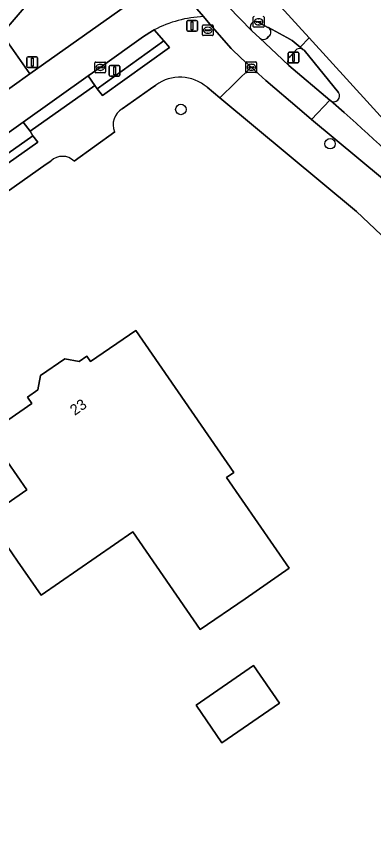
# Model space of a CAD drawing. Extents: x 161347 to 161881, y 382161 to 382804.
# Drawn here: x 161536.2 to 161569.6, y 382662 to 382738.8 of the extents above; entities that cross this region are included whole.
import ezdxf

# ---------------------------------------------------------------- set-up
doc = ezdxf.new("R2010")
doc.units = 0
for name, color, linetype in [('IMGEO_Berm_groen', 7, 'Continuous'), ('IMGEO_Boom', 7, 'Continuous'), ('IMGEO_Erf', 7, 'Continuous'), ('IMGEO_Fietspad_gesloten', 7, 'Continuous'), ('IMGEO_Groenvoorziening', 7, 'Continuous'), ('IMGEO_Haag', 7, 'Continuous'), ('IMGEO_Kolk', 7, 'Continuous'), ('IMGEO_Pand', 7, 'Continuous'), ('IMGEO_Pand_nummerreeks', 7, 'Continuous'), ('IMGEO_Rijbaan_lokaal_gesloten', 7, 'Continuous'), ('IMGEO_Rijbaan_lokaal_open', 7, 'Continuous'), ('IMGEO_Rioolput', 7, 'Continuous'), ('IMGEO_Verkeersbordpaal', 7, 'Continuous'), ('IMGEO_Verkeerseiland_groen', 7, 'Continuous'), ('IMGEO_Verkeerseiland_open', 7, 'Continuous'), ('IMGEO_Verkeersregelinstallatiepaal', 7, 'Continuous'), ('IMGEO_Voetpad_open', 7, 'Continuous')]:
    doc.layers.add(name, color=color, linetype=linetype)

msp = doc.modelspace()

# ---------------------------------------------------------------- linework, layer by layer
at = {"layer": 'IMGEO_Berm_groen'}
for points in [[(161534.886, 382737.147), (161537.494, 382733.394), (161546.454, 382739.715), (161546.949, 382740.061), (161542.143, 382745.603)], [(161537.789, 382727.63), (161537.522, 382728.039), (161536.889, 382728.907), (161530.645, 382724.485), (161516.475, 382714.369), (161503.123, 382704.778), (161491.34, 382696.368), (161486.926, 382693.195), (161487.602, 382692.215)]]:
    msp.add_lwpolyline(points, close=True, dxfattribs=at)
at = {"layer": 'IMGEO_Boom'}
for centre in [(161551.614, 382730.079), (161565.556, 382726.881)]:
    msp.add_circle(centre, 0.489, dxfattribs=at)
at = {"layer": 'IMGEO_Erf'}
for points in [[(161549.265, 382732.364), (161548.766, 382732.008), (161546.132, 382730.129)], [(161591.856, 382694.988), (161571.485, 382717.274), (161568.031, 382720.568), (161555.239, 382731.179), (161554.063, 382732.154)], [(161545.428, 382728.002), (161541.642, 382725.254)], [(161539.475, 382725.265), (161539.023, 382724.966), (161500, 382697.359), (161489.273, 382689.77), (161487.851, 382688.777), (161486.262, 382687.566), (161485.031, 382686.717), (161484.889, 382686.908), (161471.792, 382677.655), (161467.896, 382674.919)]]:
    msp.add_lwpolyline(points, dxfattribs=at)
for points in [[(161547.134, 382690.644), (161538.55, 382684.721), (161536.362, 382687.892), (161533.522, 382692.007), (161537.207, 382694.55), (161533.585, 382699.798), (161537.692, 382702.632), (161537.282, 382703.227), (161538.264, 382703.904), (161538.508, 382705.238), (161540.757, 382706.79), (161542.108, 382706.542), (161542.834, 382707.043), (161543.182, 382706.537), (161547.41, 382709.455), (161556.566, 382696.187), (161555.875, 382695.71), (161561.721, 382687.24), (161557.606, 382684.4), (161553.431, 382681.519)], [(161553.033, 382674.455), (161558.398, 382678.157), (161560.821, 382674.646), (161555.456, 382670.944)]]:
    msp.add_lwpolyline(points, close=True, dxfattribs=at)
for centre, radius, start, end in [((161551.531, 382729.212), 3.882, 49.28296, 125.70476), ((161546.958, 382728.676), 1.672, 119.61136, 203.76135), ((161540.553, 382724.161), 1.543, 45.0978, 134.32052)]:
    msp.add_arc(centre, radius, start, end, dxfattribs=at)
at = {"layer": 'IMGEO_Fietspad_gesloten'}
for points in [[(161540.187, 382749.988), (161538.613, 382748.064), (161536.523, 382745.605), (161531.663, 382739.885), (161530.446, 382738.453), (161529.536, 382737.287), (161529.183, 382736.797), (161528.989, 382736.528), (161532.246, 382733.831), (161533.12, 382735), (161534.886, 382737.147), (161542.143, 382745.603), (161544.199, 382748.164)], [(161545.564, 382748.154), (161550.263, 382742.785), (161550.342, 382742.676), (161553.736, 382738.754), (161554.324, 382738.058), (161556.318, 382735.787), (161557.247, 382734.883), (161558.194, 382734.023), (161559.548, 382732.78), (161562.685, 382730.093), (161563.827, 382729.146), (161565.541, 382730.953), (161561.715, 382734.192), (161560.548, 382735.286), (161558.99, 382736.745), (161558.259, 382737.416), (161558.212, 382737.464), (161552.779, 382743.059), (161547.812, 382748.777)], [(161566.876, 382729.794), (161565.588, 382730.912), (161565.541, 382730.953), (161563.827, 382729.146), (161570.459, 382723.644)]]:
    msp.add_lwpolyline(points, dxfattribs=at)
msp.add_arc((161490.366, 382642.402), 116.151, 42.95321, 48.79823, dxfattribs=at)
at = {"layer": 'IMGEO_Groenvoorziening'}
for points in [[(161550.024, 382736.474), (161549.126, 382737.515), (161548.976, 382737.414), (161548.114, 382736.89), (161544.081, 382734.01), (161542.938, 382733.228), (161543.561, 382732.331), (161543.803, 382732.012)], [(161550.547, 382735.868), (161550.024, 382736.474), (161543.803, 382732.012), (161544.286, 382731.374)], [(161537.789, 382727.63), (161487.602, 382692.215), (161488.093, 382691.571), (161538.259, 382727.022)]]:
    msp.add_lwpolyline(points, close=True, dxfattribs=at)
at = {"layer": 'IMGEO_Haag'}
msp.add_lwpolyline([(161550.547, 382735.868), (161550.024, 382736.474), (161543.803, 382732.012), (161544.286, 382731.374)], close=True, dxfattribs=at)
at = {"layer": 'IMGEO_Kolk'}
for p, q in [((161558.382, 382737.84), (161558.382, 382738.692)), ((161558.87, 382738.546), (161558.895, 382738.546)), ((161559.383, 382738.692), (161559.383, 382737.84)), ((161559.309, 382737.766), (161558.457, 382737.766)), ((161558.641, 382738.26), (161558.641, 382738.272)), ((161559.079, 382738.223), (161558.681, 382738.223)), ((161558.684, 382738.309), (161559.082, 382738.309)), ((161558.893, 382737.986), (161558.868, 382737.986)), ((161559.125, 382738.272), (161559.125, 382738.26)), ((161543.58, 382733.584), (161543.58, 382734.436)), ((161543.655, 382734.51), (161544.507, 382734.51)), ((161543.839, 382734.004), (161543.839, 382734.016)), ((161544.277, 382733.967), (161543.879, 382733.967)), ((161543.882, 382734.053), (161544.28, 382734.053)), ((161544.068, 382734.29), (161544.093, 382734.29)), ((161544.323, 382734.016), (161544.323, 382734.004)), ((161544.581, 382734.436), (161544.581, 382733.584)), ((161557.693, 382733.597), (161557.693, 382734.449)), ((161557.768, 382734.523), (161558.62, 382734.523)), ((161557.952, 382734.017), (161557.952, 382734.029)), ((161558.39, 382733.98), (161557.992, 382733.98)), ((161557.995, 382734.066), (161558.393, 382734.066)), ((161558.181, 382734.303), (161558.206, 382734.303)), ((161558.436, 382734.029), (161558.436, 382734.017)), ((161558.694, 382734.449), (161558.694, 382733.597)), ((161544.507, 382733.51), (161543.655, 382733.51)), ((161544.091, 382733.73), (161544.066, 382733.73)), ((161558.62, 382733.523), (161557.768, 382733.523)), ((161558.204, 382733.743), (161558.179, 382733.743))]:
    msp.add_line(p, q, dxfattribs=at)
for points in [[(161558.382, 382737.84), (161558.382, 382738.692)], [(161559.383, 382738.692), (161559.383, 382737.84)], [(161559.309, 382737.766), (161558.457, 382737.766)], [(161543.58, 382733.584), (161543.58, 382734.436)], [(161543.655, 382734.51), (161544.507, 382734.51)], [(161544.581, 382734.436), (161544.581, 382733.584)], [(161557.693, 382733.597), (161557.693, 382734.449)], [(161557.768, 382734.523), (161558.62, 382734.523)], [(161558.694, 382734.449), (161558.694, 382733.597)], [(161544.507, 382733.51), (161543.655, 382733.51)], [(161558.62, 382733.523), (161557.768, 382733.523)]]:
    msp.add_lwpolyline(points, dxfattribs=at)
for centre, radius, start, end in [((161558.459, 382738.69), 0.0765, 91.55205, 178.44795), ((161558.459, 382738.69), 0.0765, 91.55205, 178.44795), ((161559.307, 382738.69), 0.0765, 1.55205, 88.44795), ((161559.307, 382738.69), 0.0765, 1.55205, 88.44795), ((161558.459, 382737.842), 0.0765, 181.55205, 268.44795), ((161558.459, 382737.842), 0.0765, 181.55205, 268.44795), ((161558.681, 382738.269), 0.0403, 85.87752, 175.75265), ((161558.678, 382738.259), 0.0366, 178.93798, 274.71019), ((161559.082, 382738.266), 0.043, 264.86636, 352.45326), ((161559.086, 382738.271), 0.0386, 1.73085, 96.63898), ((161559.307, 382737.842), 0.0765, 271.55205, 358.44795), ((161559.307, 382737.842), 0.0765, 271.55205, 358.44795), ((161543.657, 382734.434), 0.0765, 91.55205, 178.44795), ((161543.657, 382734.434), 0.0765, 91.55205, 178.44795), ((161543.879, 382734.013), 0.0403, 85.87752, 175.75265), ((161543.876, 382734.003), 0.0366, 178.93798, 274.71019), ((161544.28, 382734.01), 0.043, 264.86636, 352.45326), ((161544.284, 382734.015), 0.0386, 1.73085, 96.63898), ((161544.505, 382734.434), 0.0765, 1.55205, 88.44795), ((161544.505, 382734.434), 0.0765, 1.55205, 88.44795), ((161557.77, 382734.447), 0.0765, 91.55205, 178.44795), ((161557.77, 382734.447), 0.0765, 91.55205, 178.44795), ((161557.992, 382734.026), 0.0403, 85.87752, 175.75265), ((161557.989, 382734.016), 0.0366, 178.93798, 274.71019), ((161558.393, 382734.023), 0.043, 264.86636, 352.45326), ((161558.397, 382734.028), 0.0386, 1.73085, 96.63898), ((161558.618, 382734.447), 0.0765, 1.55205, 88.44795), ((161558.618, 382734.447), 0.0765, 1.55205, 88.44795), ((161543.657, 382733.586), 0.0765, 181.55205, 268.44795), ((161543.657, 382733.586), 0.0765, 181.55205, 268.44795), ((161544.505, 382733.586), 0.0765, 271.55205, 358.44795), ((161544.505, 382733.586), 0.0765, 271.55205, 358.44795), ((161557.77, 382733.599), 0.0765, 181.55205, 268.44795), ((161557.77, 382733.599), 0.0765, 181.55205, 268.44795), ((161558.618, 382733.599), 0.0765, 271.55205, 358.44795), ((161558.618, 382733.599), 0.0765, 271.55205, 358.44795)]:
    msp.add_arc(centre, radius, start, end, dxfattribs=at)
for centre, major_axis, ratio, start_param, end_param in [((161558.869, 382738.266), (-0.387, 0.002), 0.722429, 4.712389, 7.853982), ((161558.894, 382738.266), (-0.39, 0.002), 0.717154, 1.570796, 4.712389), ((161544.067, 382734.01), (-0.387, 0.002), 0.722429, 4.712389, 7.853982), ((161544.092, 382734.01), (-0.39, 0.002), 0.717154, 1.570796, 4.712389), ((161558.18, 382734.023), (-0.387, 0.002), 0.722429, 4.712389, 7.853982), ((161558.205, 382734.023), (-0.39, 0.002), 0.717154, 1.570796, 4.712389)]:
    msp.add_ellipse(centre, major_axis=major_axis, ratio=ratio, start_param=start_param, end_param=end_param, dxfattribs=at)
at = {"layer": 'IMGEO_Pand'}
for points in [[(161557.606, 382684.4), (161561.721, 382687.24), (161555.875, 382695.71), (161556.566, 382696.187), (161547.41, 382709.455), (161543.182, 382706.537), (161542.834, 382707.043), (161542.108, 382706.542), (161540.757, 382706.79), (161538.508, 382705.238), (161538.264, 382703.904), (161537.282, 382703.227), (161537.692, 382702.632), (161533.585, 382699.798), (161537.207, 382694.55), (161533.522, 382692.007), (161536.362, 382687.892), (161538.55, 382684.721), (161547.134, 382690.644), (161553.431, 382681.519)], [(161555.456, 382670.944), (161560.821, 382674.646), (161558.398, 382678.157), (161553.033, 382674.455)]]:
    msp.add_lwpolyline(points, close=True, dxfattribs=at)
at = {"layer": 'IMGEO_Rijbaan_lokaal_gesloten'}
for points in [[(161563.602, 382736.77), (161557.309, 382743.681), (161552.127, 382749.763), (161549.582, 382752.75), (161549.032, 382752.282)], [(161556.097, 382742.8), (161553.042, 382742.885), (161552.894, 382742.953), (161552.779, 382743.059), (161558.212, 382737.464)], [(161558.782, 382738.249), (161559.748, 382737.749), (161559.798, 382737.722), (161561.514, 382736.792), (161562, 382736.519), (161562.401, 382736.214), (161562.771, 382735.897), (161563.602, 382736.77)], [(161563.602, 382736.77), (161562.771, 382735.897), (161563.011, 382735.691), (161563.119, 382735.603), (161566.328, 382731.665)], [(161780.196, 382571.153), (161779.525, 382578.285), (161728.827, 382571.874), (161701.238, 382588.176), (161661.586, 382630.771), (161622.627, 382671.947), (161592.087, 382705.487), (161563.602, 382736.77)], [(161565.588, 382730.912), (161566.876, 382729.794)]]:
    msp.add_lwpolyline(points, dxfattribs=at)
for centre, radius, start, end in [((161558.592, 382737.788), 0.499, 67.55615, 220.47594), ((161565.912, 382731.333), 0.532, 232.38965, 38.6081), ((161490.366, 382642.402), 116.151, 42.95321, 48.79823)]:
    msp.add_arc(centre, radius, start, end, dxfattribs=at)
at = {"layer": 'IMGEO_Rijbaan_lokaal_open'}
for points in [[(161553.736, 382738.754), (161550.342, 382742.676), (161550.404, 382742.557)], [(161546.949, 382740.061), (161546.454, 382739.715), (161537.494, 382733.394), (161534.16, 382731.042), (161520.561, 382721.294), (161496.406, 382703.987), (161461.177, 382678.951), (161463.154, 382676.198), (161464.586, 382677.241), (161481.225, 382689.112), (161481.611, 382689.399), (161486.926, 382693.195), (161491.34, 382696.368), (161503.123, 382704.778), (161516.475, 382714.369)], [(161516.475, 382714.369), (161530.645, 382724.485), (161536.889, 382728.907), (161542.938, 382733.228), (161544.081, 382734.01), (161548.114, 382736.89), (161548.976, 382737.414), (161549.126, 382737.515)]]:
    msp.add_lwpolyline(points, dxfattribs=at)
msp.add_arc((161554.179, 382727.909), 10.854, 92.34047, 117.74658, dxfattribs=at)
at = {"layer": 'IMGEO_Rioolput'}
for p, q in [((161553.63, 382737.053), (161553.63, 382737.905)), ((161553.705, 382737.979), (161554.557, 382737.979)), ((161554.118, 382737.759), (161554.143, 382737.759)), ((161554.631, 382737.905), (161554.631, 382737.053)), ((161554.557, 382736.979), (161553.705, 382736.979)), ((161553.889, 382737.473), (161553.889, 382737.485)), ((161554.327, 382737.436), (161553.929, 382737.436)), ((161553.932, 382737.522), (161554.33, 382737.522)), ((161554.141, 382737.199), (161554.116, 382737.199)), ((161554.373, 382737.485), (161554.373, 382737.473))]:
    msp.add_line(p, q, dxfattribs=at)
for points in [[(161553.63, 382737.053), (161553.63, 382737.905)], [(161553.705, 382737.979), (161554.557, 382737.979)], [(161554.631, 382737.905), (161554.631, 382737.053)], [(161554.557, 382736.979), (161553.705, 382736.979)]]:
    msp.add_lwpolyline(points, dxfattribs=at)
for centre, radius, start, end in [((161553.707, 382737.903), 0.0765, 91.55205, 178.44795), ((161553.707, 382737.903), 0.0765, 91.55205, 178.44795), ((161554.555, 382737.903), 0.0765, 1.55205, 88.44795), ((161554.555, 382737.903), 0.0765, 1.55205, 88.44795), ((161553.707, 382737.055), 0.0765, 181.55205, 268.44795), ((161553.707, 382737.055), 0.0765, 181.55205, 268.44795), ((161553.929, 382737.482), 0.0403, 85.87752, 175.75265), ((161553.926, 382737.472), 0.0366, 178.93798, 274.71019), ((161554.33, 382737.479), 0.043, 264.86636, 352.45326), ((161554.334, 382737.484), 0.0386, 1.73085, 96.63898), ((161554.555, 382737.055), 0.0765, 271.55205, 358.44795), ((161554.555, 382737.055), 0.0765, 271.55205, 358.44795)]:
    msp.add_arc(centre, radius, start, end, dxfattribs=at)
for centre, major_axis, ratio, start_param, end_param in [((161554.117, 382737.479), (-0.387, 0.002), 0.722429, 4.712389, 7.853982), ((161554.142, 382737.479), (-0.39, 0.002), 0.717154, 1.570796, 4.712389)]:
    msp.add_ellipse(centre, major_axis=major_axis, ratio=ratio, start_param=start_param, end_param=end_param, dxfattribs=at)
at = {"layer": 'IMGEO_Verkeersbordpaal'}
for p, q in [((161537.232, 382734.099), (161537.232, 382734.899)), ((161537.232, 382734.899), (161537.232, 382734.099)), ((161537.332, 382734.999), (161538.122, 382734.999)), ((161538.122, 382734.999), (161537.332, 382734.999)), ((161538.222, 382734.899), (161538.222, 382734.099)), ((161538.222, 382734.099), (161538.222, 382734.899)), ((161538.122, 382733.999), (161537.332, 382733.999)), ((161537.332, 382733.999), (161538.122, 382733.999)), ((161544.928, 382733.296), (161544.928, 382734.096)), ((161544.928, 382734.096), (161544.928, 382733.296)), ((161545.028, 382734.196), (161545.818, 382734.196)), ((161545.818, 382734.196), (161545.028, 382734.196)), ((161545.918, 382734.096), (161545.918, 382733.296)), ((161545.918, 382733.296), (161545.918, 382734.096)), ((161545.818, 382733.196), (161545.028, 382733.196)), ((161545.028, 382733.196), (161545.818, 382733.196))]:
    msp.add_line(p, q, dxfattribs=at)
for points in [[(161537.652, 382734.874), (161537.802, 382734.874), (161537.802, 382734.124), (161537.652, 382734.124), (161537.652, 382734.874)], [(161545.348, 382734.071), (161545.498, 382734.071), (161545.498, 382733.321), (161545.348, 382733.321), (161545.348, 382734.071)]]:
    msp.add_lwpolyline(points, dxfattribs=at)
for centre, start, end in [((161537.332, 382734.899), 90, 180), ((161537.332, 382734.899), 90, 180), ((161538.122, 382734.899), 0, 90), ((161538.122, 382734.899), 360, 90), ((161537.332, 382734.099), 180, 270), ((161537.332, 382734.099), 180, 270), ((161538.122, 382734.099), 270, 0), ((161538.122, 382734.099), 270, 0), ((161545.028, 382734.096), 90, 180), ((161545.028, 382734.096), 90, 180), ((161545.818, 382734.096), 0, 90), ((161545.818, 382734.096), 360, 90), ((161545.028, 382733.296), 180, 270), ((161545.028, 382733.296), 180, 270), ((161545.818, 382733.296), 270, 0), ((161545.818, 382733.296), 270, 0)]:
    msp.add_arc(centre, 0.1, start, end, dxfattribs=at)
at = {"layer": 'IMGEO_Verkeerseiland_groen'}
for points in [[(161562.451, 382735.698), (161561.822, 382735.037), (161561.71, 382734.919)], [(161563.119, 382735.603), (161563.011, 382735.691)], [(161566.328, 382731.665), (161563.119, 382735.603)], [(161561.715, 382734.192), (161565.541, 382730.953), (161565.588, 382730.912)]]:
    msp.add_lwpolyline(points, dxfattribs=at)
for centre, radius, start, end in [((161562.725, 382735.229), 0.543, 58.23597, 120.33171), ((161562.138, 382734.558), 0.56, 139.91507, 220.87303), ((161565.912, 382731.333), 0.532, 232.38965, 38.6081)]:
    msp.add_arc(centre, radius, start, end, dxfattribs=at)
at = {"layer": 'IMGEO_Verkeerseiland_open'}
for points in [[(161559.798, 382737.722), (161559.748, 382737.749), (161558.782, 382738.249)], [(161558.212, 382737.464), (161558.259, 382737.416), (161558.99, 382736.745)], [(161559.641, 382736.71), (161559.84, 382736.912)]]:
    msp.add_lwpolyline(points, dxfattribs=at)
for centre, radius, start, end in [((161558.592, 382737.788), 0.499, 67.55615, 220.47594), ((161559.538, 382737.302), 0.494, 307.71919, 58.21728), ((161559.337, 382737.131), 0.519, 228.05477, 305.79032)]:
    msp.add_arc(centre, radius, start, end, dxfattribs=at)
at = {"layer": 'IMGEO_Verkeersregelinstallatiepaal'}
for p, q in [((161552.166, 382737.48), (161552.166, 382738.28)), ((161552.166, 382738.28), (161552.166, 382737.48)), ((161552.266, 382738.38), (161553.056, 382738.38)), ((161553.056, 382738.38), (161552.266, 382738.38)), ((161553.156, 382738.28), (161553.156, 382737.48)), ((161553.156, 382737.48), (161553.156, 382738.28)), ((161553.056, 382737.38), (161552.266, 382737.38)), ((161552.266, 382737.38), (161553.056, 382737.38)), ((161561.641, 382734.536), (161561.641, 382735.336)), ((161561.641, 382735.336), (161561.641, 382734.536)), ((161561.741, 382735.436), (161562.531, 382735.436)), ((161562.531, 382735.436), (161561.741, 382735.436)), ((161562.631, 382735.336), (161562.631, 382734.536)), ((161562.631, 382734.536), (161562.631, 382735.336)), ((161562.531, 382734.436), (161561.741, 382734.436)), ((161561.741, 382734.436), (161562.531, 382734.436))]:
    msp.add_line(p, q, dxfattribs=at)
for points in [[(161552.586, 382738.255), (161552.736, 382738.255), (161552.736, 382737.505), (161552.586, 382737.505), (161552.586, 382738.255)], [(161562.061, 382735.311), (161562.211, 382735.311), (161562.211, 382734.561), (161562.061, 382734.561), (161562.061, 382735.311)]]:
    msp.add_lwpolyline(points, dxfattribs=at)
for centre, start, end in [((161552.266, 382738.28), 90, 180), ((161552.266, 382738.28), 90, 180), ((161553.056, 382738.28), 0, 90), ((161553.056, 382738.28), 360, 90), ((161552.266, 382737.48), 180, 270), ((161552.266, 382737.48), 180, 270), ((161553.056, 382737.48), 270, 0), ((161553.056, 382737.48), 270, 0), ((161561.741, 382735.336), 90, 180), ((161561.741, 382735.336), 90, 180), ((161562.531, 382735.336), 0, 90), ((161562.531, 382735.336), 360, 90), ((161561.741, 382734.536), 180, 270), ((161561.741, 382734.536), 180, 270), ((161562.531, 382734.536), 270, 0), ((161562.531, 382734.536), 270, 0)]:
    msp.add_arc(centre, 0.1, start, end, dxfattribs=at)
at = {"layer": 'IMGEO_Voetpad_open'}
for points in [[(161554.063, 382732.154), (161555.239, 382731.179), (161558.194, 382734.023), (161557.247, 382734.883), (161556.318, 382735.787), (161554.324, 382738.058), (161553.736, 382738.754)], [(161562.401, 382736.214), (161562, 382736.519), (161561.514, 382736.792), (161559.798, 382737.722)], [(161549.126, 382737.515), (161550.024, 382736.474), (161550.547, 382735.868), (161544.286, 382731.374), (161543.803, 382732.012), (161543.561, 382732.331), (161537.522, 382728.039), (161537.789, 382727.63), (161538.259, 382727.022), (161488.093, 382691.571), (161487.602, 382692.215), (161482.326, 382688.441), (161482.783, 382687.789), (161462.528, 382673.52), (161462.097, 382674.118), (161461.489, 382674.961), (161461.142, 382674.732)], [(161559.84, 382736.912), (161559.641, 382736.71)], [(161558.99, 382736.745), (161560.548, 382735.286), (161561.715, 382734.192)], [(161563.011, 382735.691), (161562.771, 382735.897), (161562.401, 382736.214)], [(161561.71, 382734.919), (161561.822, 382735.037), (161562.451, 382735.698)], [(161570.459, 382723.644), (161563.827, 382729.146), (161562.685, 382730.093), (161559.548, 382732.78), (161558.194, 382734.023), (161555.239, 382731.179), (161568.031, 382720.568), (161571.485, 382717.274), (161591.856, 382694.988), (161613.021, 382671.42), (161613.19, 382671.62), (161617.321, 382666.942), (161628.148, 382654.156)], [(161546.132, 382730.129), (161548.766, 382732.008), (161549.265, 382732.364)], [(161541.642, 382725.254), (161545.428, 382728.002)], [(161467.896, 382674.919), (161471.792, 382677.655), (161484.889, 382686.908), (161485.031, 382686.717), (161486.262, 382687.566), (161487.851, 382688.777), (161489.273, 382689.77), (161500, 382697.359), (161539.023, 382724.966), (161539.475, 382725.265)]]:
    msp.add_lwpolyline(points, dxfattribs=at)
for points in [[(161537.494, 382733.394), (161534.886, 382737.147), (161533.12, 382735), (161532.246, 382733.831), (161532.366, 382733.661), (161534.16, 382731.042)], [(161543.561, 382732.331), (161542.938, 382733.228), (161536.889, 382728.907), (161537.522, 382728.039)]]:
    msp.add_lwpolyline(points, close=True, dxfattribs=at)
for centre, radius, start, end in [((161554.179, 382727.909), 10.854, 92.34047, 117.74658), ((161559.538, 382737.302), 0.494, 307.71919, 58.21728), ((161559.337, 382737.131), 0.519, 228.05477, 305.79032), ((161562.725, 382735.229), 0.543, 58.23597, 120.33171), ((161562.138, 382734.558), 0.56, 139.91507, 220.87303), ((161551.531, 382729.212), 3.882, 49.28296, 125.70476), ((161546.958, 382728.676), 1.672, 119.61136, 203.76135), ((161540.553, 382724.161), 1.543, 45.0978, 134.32052)]:
    msp.add_arc(centre, radius, start, end, dxfattribs=at)

# ---------------------------------------------------------------- texts
at = {"layer": 'IMGEO_Pand_nummerreeks'}
msp.add_text('23', height=1, rotation=34.93496, dxfattribs=at).set_placement((161541.698, 382701.464))

doc.saveas('drawing.dxf')
